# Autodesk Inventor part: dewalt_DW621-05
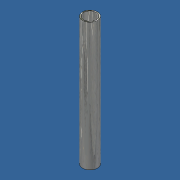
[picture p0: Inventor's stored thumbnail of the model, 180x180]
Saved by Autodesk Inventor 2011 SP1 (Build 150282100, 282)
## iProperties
Created: 2011-02
Part Number: dewalt_DW621-05
Material: 1.0037 St 37-2 / S235JR
Catalog Web Link: www.mittelmeyer.de
Document SubType Name: Modellieren
Designer: TMT
Manufacturer: Standard
Standards Organization: Custom
Density: 1 g/cm^3
Author: TMT
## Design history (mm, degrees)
sketch "Skizze2"
  geometry: C1 r 14 at (0, 0); 1 further point
  constraints: 1 centre point, 1 coincident
  dimensions: "d5" = 28 diameter of C1 (= durchmesser_01)
extrude "Extrusion2" new body sketch "Skizze2" distance "d6" = 240 (= hoehe_01); taper "d7" = 0 deg
feature "Wandstärke1" dims "d8" = 2
node "Volumenkörper1"
node "Volumenkörpern"
node "Oberflächenkörpern"
other parameters: "durchmesser_01" = 28 [user parameter; used in 1 equation term], "hoehe_01" = 240 [user parameter; used in 1 equation term]
